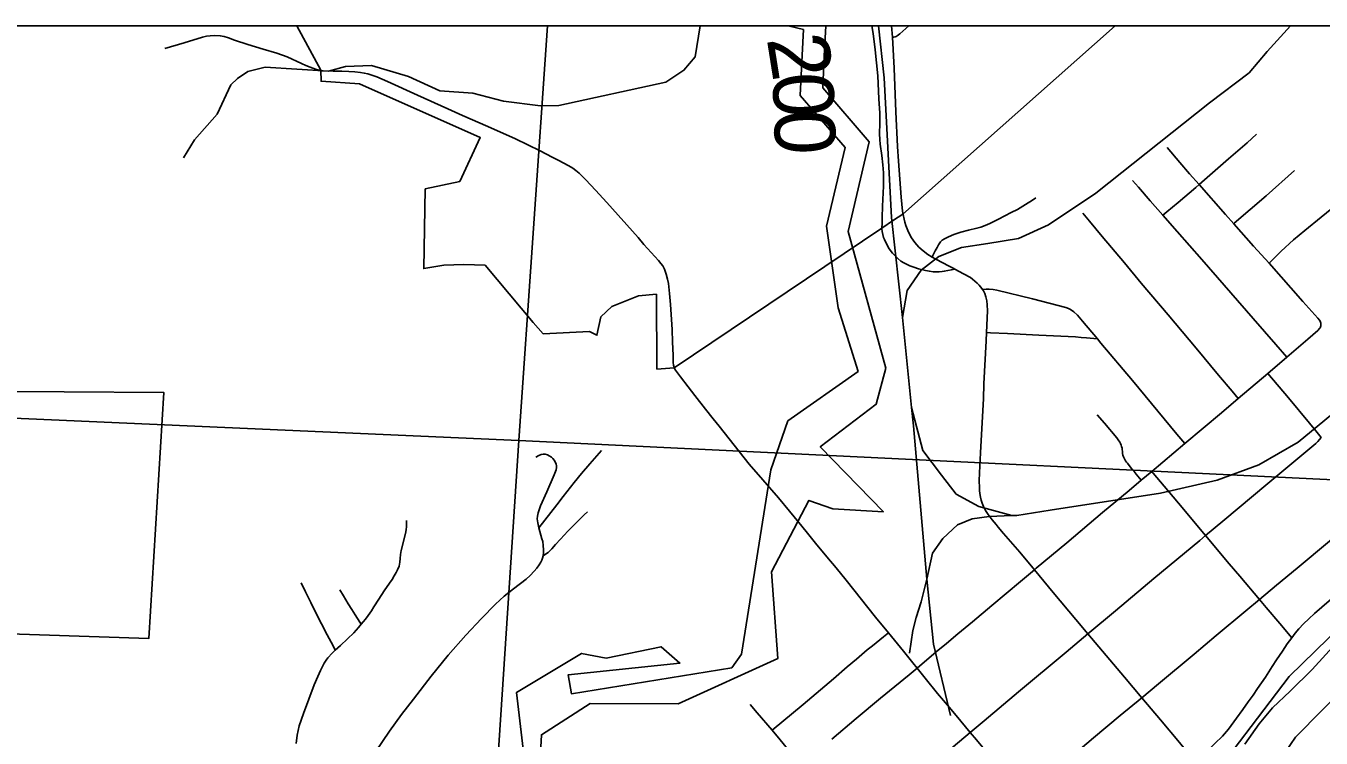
# Model space of a CAD drawing. Extents: x 21.4 to 65.3, y 4 to 26.
# Drawn here: x 27.146 to 28.362, y 24.185 to 24.854 of the extents above; entities that cross this region are included whole.
import ezdxf

# ---------------------------------------------------------------- set-up
doc = ezdxf.new("R2010")
doc.units = 0
for name, color, linetype in [('Default', 7, 'Continuous'), ('GM_X_City_Street', 7, 'Continuous'), ('GM_X_County_Road', 7, 'Continuous'), ('GM_X_Major_River', 7, 'Continuous'), ('GM_X_Minor_River', 7, 'Continuous'), ('GM_X_Rail_Line', 7, 'Continuous'), ('GM_X_Section', 7, 'Continuous'), ('GM_X_State_Route', 7, 'Continuous'), ('GM_X_Township_Road', 7, 'Continuous'), ('GM_X_Township_Road_Text', 7, 'Continuous'), ('SH_Cut_Line', 7, 'Continuous'), ('SH_Data', 7, 'Continuous')]:
    doc.layers.add(name, color=color, linetype=linetype)

msp = doc.modelspace()

# ---------------------------------------------------------------- linework, layer by layer
at = {"layer": 'Default'}
for points in [[(29.9103, 24.8542), (26.6018, 24.8542), (26.5741, 24.3781), (26.5734, 24.3737), (26.5732, 24.3694), (26.5731, 24.3659), (26.5731, 24.3616), (26.5731, 24.358), (26.5731, 24.3575), (26.5729, 24.3464), (26.5729, 24.3421), (26.5728, 24.3278), (26.5721, 24.3116), (26.5716, 24.3007), (26.5714, 24.2916), (26.571, 24.2838), (26.5253, 23.5099), (26.5201, 23.4302), (26.5076, 23.2181), (26.4968, 23.0532), (26.4915, 22.9722), (26.4573, 22.45), (26.3906, 21.3613)], [(29.9103, 24.8542), (28.1689, 24.8542), (27.9696, 24.6775), (27.961, 24.6717), (27.9498, 24.6641), (27.755, 24.533), (27.7388, 24.5319), (27.7382, 24.6021), (27.7215, 24.6007), (27.6963, 24.5907), (27.6861, 24.5808), (27.6824, 24.5637), (27.6755, 24.5671), (27.632, 24.5649), (27.6226, 24.5756), (27.5774, 24.6296), (27.5575, 24.6302), (27.5386, 24.6293), (27.5199, 24.6263), (27.5212, 24.7011), (27.5536, 24.708), (27.5728, 24.7492), (27.4594, 24.7998), (27.4235, 24.8021), (27.4232, 24.8127), (27.4006, 24.8542), (26.8479, 24.8542)], [(27.0885, 24.511), (27.2758, 24.51), (27.2617, 24.2788), (27.0467, 24.2862)], [(26.8806, 21.8662), (26.8662, 22.382), (26.8983, 22.4902), (26.9403, 22.6234), (27.1232, 23.0257), (27.1807, 23.1342), (27.2457, 23.2074), (27.2797, 23.2602), (27.35, 23.3198), (27.3927, 23.3695), (27.5383, 23.4966), (27.7231, 23.6491), (27.7926, 23.7076), (27.9329, 23.8039), (28.1831, 23.9937), (28.2398, 24.0415), (28.3384, 24.1861), (28.4624, 24.3121), (28.5577, 24.377), (28.648, 24.4047), (28.7897, 24.4217), (28.9262, 24.4567), (29.0418, 24.4692)], [(27.5383, 23.4966), (27.7231, 23.6491), (27.7926, 23.7076), (27.9329, 23.8039), (28.1831, 23.9937), (28.2398, 24.0415), (28.3384, 24.1861), (28.4624, 24.3121), (28.5577, 24.377), (28.648, 24.4047), (28.7897, 24.4217), (28.9262, 24.4567), (29.0418, 24.4692)]]:
    msp.add_lwpolyline(points, dxfattribs=at)
for points in [[(27.636, 24.8542), (26.6018, 24.8542), (26.5825, 24.5101), (27.6091, 24.4648)], [(28.7062, 24.8542), (27.636, 24.8542), (27.6091, 24.4648), (28.5947, 24.4171), (28.6053, 24.419), (28.6167, 24.4221), (28.6364, 24.4256), (28.6515, 24.4275), (28.6682, 24.4295), (28.6856, 24.4375)]]:
    msp.add_lwpolyline(points, close=True, dxfattribs=at)
at = {"layer": 'GM_X_City_Street'}
for points in [[(28.3134, 24.6314), (28.3248, 24.6426), (28.3365, 24.6533), (28.3471, 24.662), (28.3624, 24.6744), (28.3758, 24.6854), (28.3939, 24.6998), (28.4048, 24.7088), (28.4211, 24.7216), (28.4339, 24.7322), (28.4425, 24.7394), (28.4697, 24.762), (28.4788, 24.7692)], [(28.2138, 24.6764), (28.2176, 24.6796), (28.2281, 24.6883), (28.2446, 24.7025), (28.2477, 24.7052), (28.2754, 24.7294), (28.2928, 24.7444), (28.3018, 24.7524)], [(28.3622, 24.5737), (28.3621, 24.5749), (28.3617, 24.5758), (28.3613, 24.5769), (28.3607, 24.5778), (28.3592, 24.5797), (28.3453, 24.5954), (28.3134, 24.6314), (28.2988, 24.6474), (28.2803, 24.6683), (28.2725, 24.6771), (28.2477, 24.7052), (28.2389, 24.7153), (28.2298, 24.726), (28.2178, 24.7399)], [(28.2803, 24.6683), (28.2808, 24.6688), (28.3106, 24.6946), (28.3374, 24.7183)], [(28.3302, 24.5432), (28.3198, 24.5551), (28.2986, 24.5794), (28.2504, 24.6347), (28.2272, 24.661), (28.2138, 24.6764), (28.2019, 24.69), (28.1909, 24.7027), (28.1854, 24.7091)], [(27.9972, 24.6371), (27.9978, 24.6384), (28.0001, 24.643), (28.0017, 24.646), (28.0031, 24.6487), (28.005, 24.6513), (28.0067, 24.6529), (28.0086, 24.6541), (28.0125, 24.656), (28.0176, 24.6582), (28.0241, 24.6603), (28.0312, 24.6622), (28.0392, 24.6642), (28.0427, 24.6651), (28.0469, 24.6668), (28.0513, 24.6686), (28.0593, 24.6725), (28.0714, 24.6788), (28.0772, 24.6818), (28.0874, 24.688), (28.0905, 24.69), (28.0945, 24.6927)], [(28.2846, 24.5042), (28.2789, 24.511), (28.266, 24.5261), (28.245, 24.5514), (28.2186, 24.5827), (28.1935, 24.6127), (28.1778, 24.6318), (28.1569, 24.6565), (28.145, 24.6707), (28.1386, 24.6782)], [(28.0444, 24.6067), (28.0479, 24.6069), (28.0508, 24.6069), (28.0545, 24.6066), (28.0578, 24.606), (28.0913, 24.5979), (28.1227, 24.5896), (28.1251, 24.5887), (28.1271, 24.5877), (28.1301, 24.5857), (28.1337, 24.5825), (28.1384, 24.5768), (28.1523, 24.5603), (28.1556, 24.5563), (28.1852, 24.521), (28.227, 24.4709), (28.2345, 24.4619)], [(27.9031, 24.1844), (27.9257, 24.2037), (27.9486, 24.2228), (27.9755, 24.2448), (27.983, 24.2511), (28.001, 24.2662), (28.0106, 24.2741), (28.0214, 24.2831), (28.0351, 24.2945), (28.0531, 24.3097), (28.0802, 24.3325), (28.0931, 24.3434), (28.0949, 24.3449), (28.1235, 24.3688), (28.1572, 24.3973), (28.1695, 24.4075), (28.182, 24.418), (28.1934, 24.4275), (28.2033, 24.4357), (28.2345, 24.4619), (28.2688, 24.4909), (28.2846, 24.5042), (28.3122, 24.5276), (28.3302, 24.5432), (28.3498, 24.56), (28.3591, 24.5682), (28.3608, 24.5699), (28.3614, 24.5707), (28.3619, 24.5717), (28.3621, 24.5726), (28.3622, 24.5737)], [(28.0481, 24.5662), (28.052, 24.566), (28.0679, 24.5652), (28.0974, 24.5637), (28.1317, 24.5621), (28.1371, 24.5616), (28.1422, 24.5611), (28.1523, 24.5603)], [(28.3624, 24.4677), (28.3573, 24.474), (28.3513, 24.4812), (28.3317, 24.5049), (28.3122, 24.5276)], [(28.1934, 24.4275), (28.1887, 24.4333), (28.1868, 24.4357), (28.1854, 24.4373), (28.182, 24.4413), (28.1804, 24.4434), (28.1797, 24.4443), (28.1788, 24.4457), (28.1781, 24.4469), (28.1767, 24.4496), (28.1763, 24.4511), (28.1759, 24.4526), (28.1757, 24.4545), (28.1755, 24.4562), (28.1754, 24.4575), (28.175, 24.4591), (28.1747, 24.4605), (28.174, 24.4619), (28.1734, 24.4633), (28.1718, 24.4654), (28.1705, 24.4673), (28.1588, 24.481), (28.152, 24.489)], [(27.6278, 24.3828), (27.6448, 24.4044), (27.6508, 24.4123), (27.6611, 24.4254), (27.6679, 24.4337), (27.6759, 24.4429), (27.6867, 24.4555)], [(27.4746, 24.1725), (27.4877, 24.1918), (27.499, 24.2076), (27.5103, 24.2219), (27.5267, 24.2436), (27.5428, 24.2633), (27.5592, 24.2819), (27.5741, 24.2978), (27.5872, 24.311), (27.5954, 24.3186), (27.6042, 24.3254), (27.616, 24.3346), (27.6197, 24.3379), (27.6235, 24.342), (27.626, 24.3449), (27.6281, 24.3479), (27.6297, 24.3504), (27.6306, 24.3523), (27.6314, 24.3544), (27.6319, 24.3565), (27.6322, 24.3595), (27.6324, 24.3621), (27.632, 24.3663), (27.6315, 24.3699), (27.6308, 24.3726), (27.6278, 24.3828), (27.6268, 24.3874), (27.6264, 24.3911), (27.6266, 24.3936), (27.6273, 24.3968), (27.6295, 24.4033), (27.6354, 24.4166), (27.6423, 24.4325), (27.644, 24.4371), (27.6444, 24.4396), (27.6444, 24.441), (27.6442, 24.4425), (27.6433, 24.4447), (27.6424, 24.4463), (27.6411, 24.4479), (27.6397, 24.449), (27.6377, 24.4505), (27.636, 24.4514), (27.6339, 24.452), (27.632, 24.452), (27.63, 24.4515), (27.6279, 24.4506), (27.6252, 24.449)], [(28.3348, 24.2795), (28.3235, 24.2928), (28.3107, 24.308), (28.3044, 24.3155), (28.286, 24.3373), (28.2759, 24.3491), (28.2539, 24.3756), (28.2283, 24.406), (28.2185, 24.4177), (28.2047, 24.434), (28.2033, 24.4357)], [(27.6319, 24.3565), (27.6342, 24.358), (27.6365, 24.3597), (27.6385, 24.3615), (27.64, 24.363), (27.6436, 24.3672), (27.6482, 24.3723), (27.6551, 24.3797), (27.6705, 24.395), (27.6736, 24.3979)], [(27.4, 24.1802), (27.4009, 24.1882), (27.4018, 24.1925), (27.403, 24.1967), (27.4068, 24.2084), (27.4119, 24.2219), (27.417, 24.2352), (27.4204, 24.2432), (27.4229, 24.2489), (27.4264, 24.2556), (27.4281, 24.2585), (27.4297, 24.2607), (27.4337, 24.2652), (27.4367, 24.2679), (27.4416, 24.2723), (27.4481, 24.2786), (27.4541, 24.2843), (27.4585, 24.2891), (27.4611, 24.2922), (27.4631, 24.2946), (27.465, 24.297), (27.4675, 24.3006), (27.4707, 24.305), (27.473, 24.3086), (27.4776, 24.3158), (27.4828, 24.3235), (27.4878, 24.3307), (27.4902, 24.3344), (27.4922, 24.3378), (27.494, 24.3409), (27.4953, 24.3435), (27.4966, 24.3469), (27.4973, 24.3505), (27.4976, 24.354), (27.4979, 24.3576), (27.4985, 24.3614), (27.5027, 24.3775), (27.5032, 24.3808), (27.5035, 24.3839), (27.5036, 24.3896)], [(27.4367, 24.2679), (27.4356, 24.2701), (27.433, 24.2753), (27.4293, 24.2824), (27.4237, 24.2926), (27.4192, 24.3017), (27.4138, 24.3128), (27.4089, 24.3227), (27.4048, 24.331)], [(27.4611, 24.2922), (27.4598, 24.2942), (27.4554, 24.3011), (27.4523, 24.306), (27.449, 24.3114), (27.4444, 24.3188), (27.4409, 24.3246)], [(27.8469, 24.1928), (27.8759, 24.217), (27.9045, 24.2411), (27.9174, 24.2522), (27.9261, 24.2595), (27.9362, 24.2681), (27.9412, 24.2721), (27.9515, 24.2804), (27.9562, 24.2842)], [(28.1332, 24.0702), (28.113, 24.0944), (28.1011, 24.1088), (28.0831, 24.1304), (28.0767, 24.138), (28.0645, 24.1526), (28.0539, 24.1654), (28.0387, 24.1837), (28.0329, 24.1906), (28.024, 24.2012), (28.0133, 24.214), (28.0022, 24.2272), (27.9906, 24.2416), (27.983, 24.2511)], [(28.2443, 24.163), (28.2413, 24.1666), (28.2295, 24.1811), (28.2114, 24.2024), (28.1939, 24.2233)], [(27.8757, 24.1597), (27.8731, 24.1618), (27.8715, 24.1634), (27.87, 24.1649), (27.8642, 24.1718), (27.8543, 24.1837), (27.8469, 24.1928), (27.833, 24.2092), (27.8263, 24.2169)]]:
    msp.add_lwpolyline(points, dxfattribs=at)
at = {"layer": 'GM_X_County_Road'}
for points in [[(28.0049, 24.1672), (28.0329, 24.1906), (28.0461, 24.2017), (28.0782, 24.2287), (28.1231, 24.2661), (28.1433, 24.2831), (28.1693, 24.3048), (28.2054, 24.3352), (28.2484, 24.371), (28.2539, 24.3756), (28.2699, 24.3889), (28.3123, 24.4243), (28.3574, 24.4619), (28.3592, 24.4638), (28.3609, 24.4657), (28.3624, 24.4677)], [(28.2443, 24.163), (28.2455, 24.164), (28.2554, 24.1733), (28.2696, 24.1872), (28.2753, 24.1937), (28.283, 24.2041), (28.2888, 24.2122), (28.2938, 24.2193), (28.2985, 24.2258), (28.3027, 24.2319), (28.31, 24.2427), (28.3164, 24.2525), (28.3205, 24.2587), (28.326, 24.267), (28.3306, 24.2739), (28.3348, 24.2795), (28.3381, 24.284), (28.3413, 24.2879), (28.3458, 24.2926), (28.3507, 24.2973), (28.356, 24.3022), (28.395, 24.3359)]]:
    msp.add_lwpolyline(points, dxfattribs=at)
at = {"layer": 'GM_X_Major_River'}
msp.add_lwpolyline([(28.7031, 24.4348), (28.6759, 24.4248), (28.5728, 24.408), (28.5305, 24.3961), (28.472, 24.364), (28.3936, 24.3029), (28.3323, 24.2431), (28.2499, 24.1349), (28.1712, 24.0519), (28.1614, 24.045), (28.1374, 24.016), (28.0782, 23.9596), (27.9994, 23.9077), (27.9621, 23.8798), (27.9068, 23.8226), (27.8936, 23.8142), (27.8705, 23.813), (27.8566, 23.808), (27.846, 23.7981), (27.831, 23.7737), (27.8227, 23.7631), (27.7398, 23.7024), (27.6426, 23.6238), (27.545, 23.5494)], dxfattribs=at)
at = {"layer": 'GM_X_Minor_River'}
for points in [[(27.7794, 24.8542), (27.7747, 24.825), (27.7641, 24.8125), (27.7471, 24.8014), (27.6466, 24.7793), (27.6295, 24.7792), (27.5947, 24.7834), (27.5659, 24.791), (27.5348, 24.7932), (27.5056, 24.8065), (27.4707, 24.8171), (27.4465, 24.8159), (27.4305, 24.8117), (27.371, 24.8155), (27.3547, 24.8113), (27.3449, 24.8048), (27.3388, 24.7987), (27.3259, 24.7713), (27.3047, 24.747), (27.2944, 24.7302)], [(27.8621, 24.8542), (27.8763, 24.8507), (27.8751, 24.8268), (27.8733, 24.7888), (27.9154, 24.7399), (27.8979, 24.666)], [(27.9182, 24.6612), (27.9381, 24.7454), (27.8945, 24.7961), (27.8959, 24.8258), (27.8973, 24.8542)], [(27.8979, 24.666), (27.909, 24.5895), (27.9276, 24.5297), (27.8618, 24.4832), (27.8457, 24.4372), (27.818, 24.2642), (27.809, 24.2512), (27.6587, 24.2268), (27.6554, 24.2446), (27.7604, 24.2557), (27.7427, 24.2711), (27.6912, 24.2604), (27.668, 24.2648), (27.607, 24.2282), (27.6181, 24.1323)], [(27.6285, 24.1536), (27.6303, 24.1885), (27.6762, 24.2178), (27.7586, 24.2174), (27.8522, 24.26), (27.8462, 24.3415), (27.8814, 24.4086), (27.9039, 24.4005), (27.9514, 24.3979), (27.8921, 24.4588), (27.9447, 24.4988), (27.9538, 24.5326), (27.9182, 24.6612)]]:
    msp.add_lwpolyline(points, dxfattribs=at)
at = {"layer": 'GM_X_Rail_Line'}
for points in [[(27.9467, 24.8542), (27.9522, 24.8054), (27.9591, 24.6741), (27.9693, 24.5803), (27.9707, 24.5679), (27.9779, 24.4957), (27.9885, 24.4555), (28.0059, 24.4321), (28.0197, 24.4145), (28.0411, 24.4029), (28.072, 24.3943), (28.0768, 24.3945), (28.108, 24.3993), (28.2114, 24.4154), (28.2646, 24.4277), (28.3037, 24.4419), (28.3409, 24.4632), (28.3784, 24.4943)], [(27.9693, 24.5803), (27.9737, 24.6056), (27.9867, 24.6247), (28.0035, 24.6376), (28.0248, 24.646), (28.0493, 24.6499), (28.0782, 24.6544), (28.1065, 24.6674), (28.1507, 24.6972), (28.2575, 24.7819), (28.2949, 24.8102), (28.3117, 24.83), (28.3336, 24.8542)], [(27.9779, 24.4957), (27.9796, 24.4787), (27.9922, 24.3346)], [(28.072, 24.3943), (28.0508, 24.3934), (28.0348, 24.3911), (28.021, 24.3857), (28.0073, 24.3728), (27.9974, 24.359), (27.9922, 24.3346)], [(27.9922, 24.3346), (27.9867, 24.3132), (27.9821, 24.2987), (27.9791, 24.2865), (27.976, 24.2652)], [(27.9922, 24.3346), (27.9985, 24.2736), (28.0144, 24.2067)]]:
    msp.add_lwpolyline(points, dxfattribs=at)
at = {"layer": 'GM_X_Section'}
msp.add_lwpolyline([(26.5825, 24.5101), (27.6091, 24.4648), (27.5486, 23.5443), (27.5415, 23.5386), (27.5313, 23.5298), (27.5214, 23.5207), (27.5097, 23.5112), (27.4908, 23.4937), (27.4682, 23.4724), (27.4508, 23.456), (27.444, 23.4496), (27.4376, 23.4427), (26.5198, 23.4854)], close=True, dxfattribs=at)
for points in [[(27.5486, 23.5443), (27.6091, 24.4648), (28.5947, 24.4171)], [(28.3766, 24.2746), (28.354, 24.2499), (28.3332, 24.2294), (28.3166, 24.2138), (28.3041, 24.1986), (28.2906, 24.1796)]]:
    msp.add_lwpolyline(points, dxfattribs=at)
at = {"layer": 'GM_X_State_Route'}
for points in [[(27.9698, 24.677), (27.9694, 24.6801), (27.9681, 24.6933), (27.9656, 24.7271), (27.9646, 24.741), (27.9632, 24.7734), (27.9615, 24.8144), (27.9598, 24.8435), (27.959, 24.8542)], [(28.0572, 24.3858), (28.0534, 24.3904), (28.0497, 24.3952), (28.0472, 24.3991), (28.0469, 24.3997), (28.0455, 24.4027), (28.0442, 24.406), (28.0432, 24.4089), (28.0426, 24.4116), (28.042, 24.4151), (28.0416, 24.4179), (28.0415, 24.4204), (28.0414, 24.4271), (28.042, 24.4409), (28.0429, 24.4592), (28.0452, 24.5039), (28.0458, 24.5181), (28.0478, 24.5584), (28.0481, 24.5662), (28.049, 24.5867), (28.0489, 24.5921), (28.0485, 24.5961), (28.0477, 24.5997), (28.0466, 24.6027), (28.0454, 24.6053), (28.0444, 24.6067), (28.0438, 24.6077), (28.0413, 24.6106), (28.0393, 24.6125), (28.0373, 24.6145), (28.0351, 24.6163), (28.033, 24.6179), (28.0267, 24.6214), (28.0226, 24.6236), (28.0184, 24.6258), (28.0176, 24.6262), (28.0131, 24.6284), (28.0005, 24.6351), (27.9972, 24.6371), (27.9932, 24.6396), (27.9888, 24.6429), (27.9847, 24.6465), (27.981, 24.6506), (27.9779, 24.6551), (27.975, 24.6604), (27.9725, 24.6667), (27.9715, 24.6698), (27.9708, 24.6726), (27.9698, 24.677)], [(28.1939, 24.2233), (28.2095, 24.2363), (28.2431, 24.2641), (28.2638, 24.2817), (28.2915, 24.3048), (28.3044, 24.3155), (28.3204, 24.3289), (28.3397, 24.345), (28.3701, 24.3704), (28.388, 24.3855), (28.4007, 24.396), (28.4134, 24.4063)], [(28.1939, 24.2233), (28.1776, 24.2427), (28.1433, 24.2831), (28.132, 24.2966), (28.1107, 24.3221), (28.0931, 24.3434), (28.0796, 24.3598), (28.0641, 24.3776), (28.0591, 24.3835), (28.0572, 24.3858)], [(27.9167, 23.9907), (27.9205, 23.9939), (27.9526, 24.0209), (27.9727, 24.0377), (27.9815, 24.0452), (28.0265, 24.0829), (28.0481, 24.1012), (28.0783, 24.1264), (28.0831, 24.1304), (28.0925, 24.1384), (28.1235, 24.1644), (28.1486, 24.1855), (28.1737, 24.2066), (28.1939, 24.2233)]]:
    msp.add_lwpolyline(points, dxfattribs=at)
at = {"layer": 'GM_X_Township_Road'}
for points in [[(27.2768, 24.833), (27.295, 24.8384), (27.3121, 24.8435), (27.3158, 24.8444), (27.3194, 24.8449), (27.3237, 24.8452), (27.3287, 24.8449), (27.3323, 24.8442), (27.3364, 24.8428), (27.3422, 24.8407), (27.3546, 24.8368), (27.369, 24.8323), (27.3819, 24.8286), (27.3915, 24.8251), (27.4049, 24.8188), (27.409, 24.8169), (27.4131, 24.8153), (27.4182, 24.8135), (27.4234, 24.8122), (27.4244, 24.8121)], [(27.95, 24.6636), (27.9501, 24.6694), (27.9502, 24.6743), (27.9506, 24.6849), (27.9514, 24.7035), (27.9515, 24.7096), (27.9514, 24.7161), (27.9509, 24.7237), (27.9499, 24.7324), (27.9483, 24.7431), (27.9479, 24.7476), (27.9478, 24.7527), (27.9479, 24.7627), (27.948, 24.7722), (27.9471, 24.7857), (27.9462, 24.8074), (27.9435, 24.8316), (27.9417, 24.847), (27.9405, 24.8542)], [(27.9598, 24.8435), (27.9613, 24.8436), (27.9623, 24.8438), (27.9634, 24.8443), (27.9644, 24.8448), (27.9669, 24.8466), (27.9753, 24.8542)], [(27.4244, 24.8121), (27.4349, 24.8117), (27.4428, 24.8115), (27.4494, 24.8112), (27.455, 24.8109), (27.4606, 24.8104), (27.4639, 24.8099), (27.4674, 24.8091), (27.4757, 24.8062), (27.4857, 24.802), (27.514, 24.789), (27.5423, 24.7763), (27.5562, 24.7701), (27.58, 24.7596)], [(27.58, 24.7596), (27.6061, 24.7482), (27.629, 24.7369), (27.6405, 24.731), (27.6465, 24.7278), (27.6506, 24.7256), (27.656, 24.7227), (27.6597, 24.7205), (27.6625, 24.7185), (27.6656, 24.716), (27.6682, 24.7134), (27.6721, 24.7097), (27.6812, 24.6999), (27.6916, 24.6884), (27.721, 24.6555), (27.7266, 24.649), (27.7368, 24.6375), (27.7403, 24.6337), (27.7423, 24.6311), (27.7442, 24.6287), (27.7458, 24.6256), (27.7475, 24.6211), (27.7488, 24.6164), (27.7495, 24.6122), (27.7506, 24.603), (27.7516, 24.5925), (27.7531, 24.569), (27.7535, 24.5573), (27.7539, 24.545), (27.7541, 24.538), (27.7544, 24.5355), (27.7552, 24.5325)], [(28.0184, 24.6258), (28.0153, 24.6252), (28.0085, 24.6237), (28.0064, 24.6234), (28.0038, 24.6231), (28.001, 24.6231), (27.998, 24.6233), (27.9945, 24.6237), (27.9909, 24.6245), (27.9842, 24.6261), (27.9798, 24.6276), (27.9762, 24.6289), (27.9731, 24.6303), (27.9705, 24.6315), (27.9678, 24.6333), (27.9649, 24.6356), (27.9626, 24.6379), (27.96, 24.6406), (27.9569, 24.6448), (27.9545, 24.6489), (27.9523, 24.6536), (27.9516, 24.6554), (27.9509, 24.6582), (27.9503, 24.6611), (27.95, 24.6636)], [(27.7552, 24.5325), (27.7562, 24.5309), (27.7609, 24.5245), (27.7681, 24.5152), (27.7744, 24.507), (27.7844, 24.4943), (27.7916, 24.4853), (27.7971, 24.4784), (27.8066, 24.4663), (27.8254, 24.4426), (27.8383, 24.4278), (27.8529, 24.4109), (27.8633, 24.3985), (27.872, 24.3879), (27.8789, 24.3794), (27.8877, 24.3684), (27.8983, 24.3557), (27.9069, 24.3453), (27.9163, 24.3336), (27.9441, 24.2988), (27.9562, 24.2842), (27.9703, 24.2671), (27.979, 24.256), (27.983, 24.2511)]]:
    msp.add_lwpolyline(points, dxfattribs=at)
at = {"layer": 'SH_Cut_Line'}
for points in [[(29.9103, 24.8542), (23.5473, 24.8542)], [(26.8806, 21.8662), (26.8662, 22.382), (26.8983, 22.4902), (26.9403, 22.6234), (27.1232, 23.0257), (27.1807, 23.1342), (27.2457, 23.2074), (27.2797, 23.2602), (27.35, 23.3198), (27.3927, 23.3695), (27.5383, 23.4966), (27.7231, 23.6491), (27.7926, 23.7076), (27.9329, 23.8039), (28.1831, 23.9937), (28.2398, 24.0415), (28.3384, 24.1861), (28.4624, 24.3121), (28.5577, 24.377), (28.648, 24.4047), (28.7897, 24.4217), (28.9262, 24.4567), (29.0418, 24.4692)]]:
    msp.add_lwpolyline(points, dxfattribs=at)
at = {"layer": 'SH_Data'}
msp.add_line((23.5473, 24.8542), (30.3473, 24.8542), dxfattribs=at)

# ---------------------------------------------------------------- texts
at = {"layer": 'GM_X_Township_Road_Text'}
for s, rotation, p in [('2', 279.0405, (27.8418, 24.8422)), ('0', 272.629, (27.8471, 24.8093)), ('0', 271.6238, (27.8487, 24.7746))]:
    msp.add_text(s, height=0.0568, rotation=rotation, dxfattribs=at).set_placement(p)

doc.saveas('drawing.dxf')
